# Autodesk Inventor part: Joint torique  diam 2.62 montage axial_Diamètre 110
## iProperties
Shininess: 64.0
Length Units: 11269
Angle Units: 11279
Time Units: 11290
Mass Units: 11283
Length Display Precision: 3
Angle Display Precision: 2
Compacted: True
Part Number: Joint torique  diam 2.62 montage axial_Diamètre 110
Document SubType Name: Modeling
Created: 2006-01
Material: Par défaut
Designer: riri
Density: 0.0
Volumn: 0.0
Area: 0.0
PropertySet Name: Model Information
Control State: 0
Master: False
Checked Out: False
Author: riri
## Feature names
1. Base1
